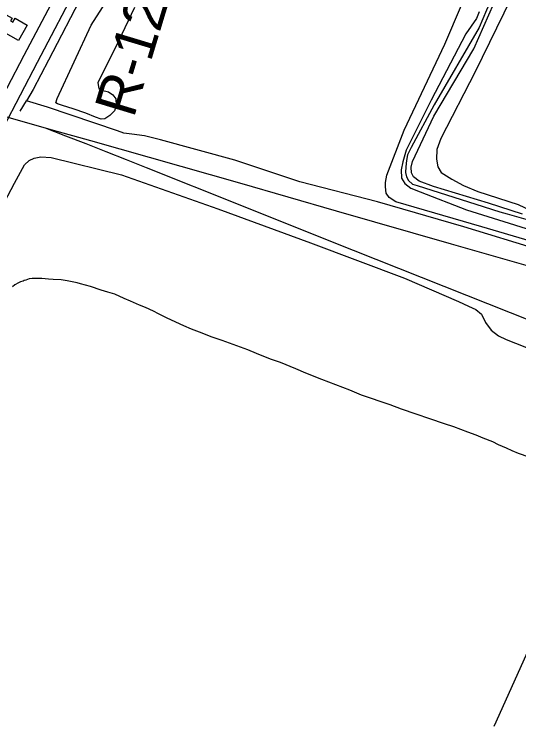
# Model space of a CAD drawing. Extents: x 3567028 to 3605064, y 510945 to 536587.
# Drawn here: x 3588639 to 3589650, y 520355 to 521776 of the extents above; entities that cross this region are included whole.
import ezdxf

# ---------------------------------------------------------------- set-up
doc = ezdxf.new("R2010")
doc.units = 0
for name, color, linetype in [('V-BLDG-OTLN', 7, 'Continuous'), ('V-RAIL-TRAK', 7, 'Continuous'), ('V-RIVR-RANG-IDEN', 7, 'Continuous'), ('V-ROAD-CNTR', 7, 'Continuous'), ('V-SITE-VEGE', 7, 'Continuous'), ('V-TOPO-SHOR', 7, 'Continuous')]:
    doc.layers.add(name, color=color, linetype=linetype)

msp = doc.modelspace()

# ---------------------------------------------------------------- linework, layer by layer
at = {"layer": 'V-BLDG-OTLN'}
msp.add_lwpolyline([(3588665.5, 521754.5), (3588648.2, 521723.7), (3588617.5, 521741), (3588614.2, 521735.2), (3588595.3, 521745.9), (3588600.1, 521754.3), (3588609.1, 521749.3), (3588623.6, 521775), (3588635.3, 521768.4), (3588632.2, 521763.1), (3588636.8, 521760.5), (3588641.2, 521768.2)], close=True, dxfattribs=at)
at = {"layer": 'V-RAIL-TRAK'}
for points in [[(3588149.4, 521708.3), (3588373.9, 521643.8), (3588624.2, 521571.2), (3588701.3, 521548.8), (3588712.7, 521545.5), (3588792.2, 521523.6), (3589090.5, 521438.9), (3589284.2, 521383.4), (3589514.3, 521317.3), (3589701.3, 521263.5)], [(3588701.3, 521548.8), (3588741.9, 521533.4), (3588782.5, 521517.8), (3588823, 521502), (3588863.3, 521486), (3588903.6, 521469.7), (3589091.4, 521395.1), (3589272.9, 521322.7), (3589499.9, 521232.4), (3589720.1, 521145.4)]]:
    msp.add_lwpolyline(points, dxfattribs=at)
at = {"layer": 'V-ROAD-CNTR'}
for points in [[(3588939.5, 522164.8), (3588685.5, 521679.8), (3588548.3, 521418.6), (3588324.5, 520986.4), (3588212.6, 520770.2), (3587956.4, 520279.2), (3587855.8, 520084.1), (3587648.7, 519691.3), (3587418.1, 519252.9), (3587233.2, 518901.5), (3587118.4, 518681.4), (3586962.3, 518388.3), (3586789.7, 518038.8)], [(3588736.5, 521841.8), (3588658.9, 521693.7), (3588521.7, 521432.4), (3588297.8, 521000.2), (3588244.5, 520897.2)]]:
    msp.add_lwpolyline(points, dxfattribs=at)
at = {"layer": 'V-SITE-VEGE'}
for p, q in [((3588660.2, 521474.9), (3588669.1, 521483.8)), ((3588669.1, 521483.8), (3588679.7, 521488.6)), ((3588679.7, 521488.6), (3588692.7, 521490.9)), ((3588692.7, 521490.9), (3588713.5, 521489.7)), ((3588713.5, 521489.7), (3588854.3, 521455.3)), ((3588640, 521438.3), (3588660.2, 521474.9)), ((3588854.3, 521455.3), (3589047.2, 521387.1)), ((3588584.9, 521335.3), (3588640, 521438.3)), ((3589047.2, 521387.1), (3589232.4, 521319)), ((3589232.4, 521319), (3589420.6, 521248.4)), ((3588648.1, 521239.4), (3588640.8, 521234.9)), ((3588651.7, 521241.2), (3588648.1, 521239.4)), ((3588654.4, 521241.6), (3588651.7, 521241.2)), ((3588657.1, 521242.5), (3588654.4, 521241.6)), ((3588659.4, 521243.8), (3588657.1, 521242.5)), ((3588662.6, 521244.2), (3588659.4, 521243.8)), ((3588669.4, 521246.9), (3588662.6, 521244.2)), ((3588675.7, 521247.8), (3588669.4, 521246.9)), ((3588694.7, 521247.6), (3588675.7, 521247.8)), ((3588708.2, 521246.6), (3588694.7, 521247.6)), ((3588717.7, 521245.7), (3588708.2, 521246.6)), ((3588733.6, 521245.1), (3588717.7, 521245.7)), ((3588745.3, 521243.2), (3588733.6, 521245.1)), ((3588765.2, 521239), (3588745.3, 521243.2)), ((3588771.9, 521237.2), (3588765.2, 521239)), ((3588792.2, 521232), (3588771.9, 521237.2)), ((3589420.6, 521248.4), (3589528.9, 521201.6)), ((3588640.8, 521234.9), (3588635.8, 521230.9)), ((3588813.4, 521224.7), (3588792.2, 521232)), ((3588827, 521220.5), (3588813.4, 521224.7)), ((3588841, 521216.3), (3588827, 521220.5)), ((3588859.9, 521207.6), (3588841, 521216.3)), ((3588872.1, 521202.6), (3588859.9, 521207.6)), ((3588890.1, 521194.7), (3588872.1, 521202.6)), ((3588902.3, 521189.7), (3588890.1, 521194.7)), ((3589528.9, 521201.6), (3589549, 521192.7)), ((3588918, 521182.3), (3588902.3, 521189.7)), ((3588928.4, 521177.3), (3588918, 521182.3)), ((3589549, 521192.7), (3589563.8, 521185.6)), ((3589563.8, 521185.6), (3589575, 521176.1)), ((3588946, 521168.1), (3588928.4, 521177.3)), ((3588979.3, 521153), (3588946, 521168.1)), ((3589575, 521176.1), (3589583.3, 521159.5)), ((3588994.6, 521146.5), (3588979.3, 521153)), ((3589583.3, 521159.5), (3589594.6, 521144.7)), ((3589010.4, 521140.1), (3588994.6, 521146.5)), ((3589036.1, 521130.4), (3589010.4, 521140.1)), ((3589594.6, 521144.7), (3589608.8, 521132.9)), ((3589056, 521124), (3589036.1, 521130.4)), ((3589106.9, 521105.1), (3589056, 521124)), ((3589608.8, 521132.9), (3589624.7, 521125.8)), ((3589624.7, 521125.8), (3589712.3, 521090.8)), ((3589124.5, 521097.7), (3589106.9, 521105.1)), ((3589152.5, 521086.7), (3589124.5, 521097.7)), ((3589172.3, 521079.8), (3589152.5, 521086.7)), ((3589203, 521067.3), (3589172.3, 521079.8)), ((3589223.2, 521058.6), (3589203, 521067.3)), ((3589255.3, 521045.7), (3589223.2, 521058.6)), ((3589311.6, 521024.1), (3589255.3, 521045.7)), ((3589335.1, 521014.4), (3589311.6, 521024.1)), ((3589391.9, 520995.1), (3589335.1, 521014.4)), ((3589414.9, 520986.3), (3589391.9, 520995.1)), ((3589501, 520957.2), (3589414.9, 520986.3)), ((3589519.5, 520950.8), (3589501, 520957.2)), ((3589547.9, 520940.6), (3589519.5, 520950.8)), ((3589564.2, 520934.2), (3589547.9, 520940.6)), ((3589578.6, 520928.7), (3589564.2, 520934.2)), ((3589598, 520920.8), (3589578.6, 520928.7)), ((3589609.2, 520915.3), (3589598, 520920.8)), ((3589625, 520908.4), (3589609.2, 520915.3)), ((3589636.7, 520902.9), (3589625, 520908.4)), ((3589649.4, 520897.9), (3589636.7, 520902.9)), ((3589670.6, 520890.5), (3589649.4, 520897.9)), ((3589604.1, 520361.1), (3589672.9, 520513.4)), ((3589600.4, 520352.1), (3589604.1, 520361.1))]:
    msp.add_line(p, q, dxfattribs=at)
for points in [[(3589657, 521376.1), (3589589.4, 521398.7), (3589479.2, 521432), (3589450.1, 521442.1), (3589438.9, 521451), (3589434.7, 521459.3), (3589434.1, 521470.6), (3589437.1, 521481.8), (3589479.3, 521572.5), (3589559.4, 521707.1), (3589599.8, 521797.8), (3589605.1, 521825.1), (3589602.2, 521840.5), (3589600.4, 521851.1), (3589600.4, 521865.4), (3589602.8, 521875.5), (3589612.9, 521889.1), (3589615, 521890.8), (3589628.7, 521902.7), (3589664.1, 521962.5)], [(3589770.8, 521293.9), (3589575.8, 521350.9), (3589403.8, 521401.4), (3589390.2, 521409.7), (3589384.3, 521418.6), (3589383.1, 521431.1), (3589383.1, 521440), (3589385.5, 521454.2), (3589419.9, 521544.3), (3589501.9, 521716.2), (3589570.7, 521878)], [(3588880.3, 521790.1), (3588847.9, 521722.5), (3588806.6, 521639.4), (3588809, 521628), (3588814.4, 521624.4), (3588828.1, 521620.8), (3588837.1, 521614.8), (3588843.1, 521607.1), (3588843.7, 521593.9), (3588840.1, 521583.1), (3588831.1, 521573.6), (3588820.9, 521567), (3588813.8, 521566.4), (3588802.4, 521570.6), (3588782.7, 521578.4), (3588757.5, 521586.8), (3588736, 521594), (3588725.8, 521597), (3588722.8, 521599.4), (3588725.2, 521607.7), (3588793.5, 521754.3), (3588861.8, 521861.3)], [(3589653.7, 521847.8), (3589633.6, 521807.8), (3589562.3, 521661.4), (3589493.5, 521528), (3589485.7, 521506.1), (3589485.1, 521486.5), (3589487.5, 521471.1), (3589494.6, 521459.9), (3589515.4, 521446.2), (3589539.1, 521433.7), (3589567.5, 521421.9), (3589648.7, 521395.7), (3589673.6, 521383.8)], [(3589570.7, 521781.4), (3589565.3, 521767.8), (3589544, 521736.9), (3589474.5, 521604.7), (3589424, 521504.6), (3589417.5, 521481.4), (3589414.5, 521465.4), (3589415.1, 521448.2), (3589421.6, 521437.6), (3589433.5, 521428.7), (3589452.5, 521420.9), (3589544.9, 521385.3), (3589739.4, 521324.7)]]:
    msp.add_lwpolyline(points, dxfattribs=at)
at = {"layer": 'V-TOPO-SHOR'}
msp.add_line((3588651.3, 521582.7), (3588663.9, 521602.8), dxfattribs=at)
for points in [[(3589341.4, 521997.5), (3589425, 521956.7), (3589560.1, 521893.2), (3589591.5, 521878.9), (3589595.7, 521871.8), (3589593.3, 521850.5), (3589595.1, 521816.1), (3589592.1, 521800.1), (3589585, 521784.6), (3589570.7, 521749.7), (3589480.5, 521595), (3589434.2, 521509.6), (3589427.1, 521495.4), (3589424.7, 521484.1), (3589423.5, 521471.1), (3589422.9, 521459.8), (3589424.7, 521450.9), (3589428.8, 521443.8), (3589437.1, 521436.7), (3589446, 521433.7), (3589564, 521396.3), (3589612, 521381.4)], [(3588837.9, 521941.9), (3588777.9, 521819.8), (3588708.4, 521684.6), (3588677.6, 521626), (3588663.9, 521602.8)], [(3591205.5, 520869.1), (3591079.3, 520900), (3590907.9, 520948.1), (3590756.1, 520994.4), (3590634, 521031.9), (3590469.8, 521081.2), (3590287.8, 521135.2), (3590133.1, 521181), (3589996.7, 521218.4), (3589853.8, 521260), (3589692.5, 521304.6), (3589539.6, 521350.9), (3589366.5, 521401.4), (3589211.1, 521441.2), (3589081.3, 521484.6), (3588932.5, 521525), (3588900.5, 521533.3), (3588875, 521536.3), (3588859, 521538.7), (3588846.5, 521543.4), (3588706, 521590.4), (3588663.9, 521602.8)], [(3589612, 521381.4), (3589626.2, 521377.2), (3589738.3, 521345.1), (3589867.5, 521309.5), (3590019.3, 521269), (3590179.4, 521219.7), (3590311, 521182.9), (3590489.4, 521127.6), (3590647.7, 521085.5), (3590798.9, 521043.9), (3590980.9, 520990.4), (3591141, 520945.2), (3591278.3, 520907)]]:
    msp.add_lwpolyline(points, dxfattribs=at)

# ---------------------------------------------------------------- texts
at = {"layer": 'V-RIVR-RANG-IDEN'}
msp.add_text('R-120.6', height=83, rotation=73.2241, dxfattribs=at).set_placement((3588878.7, 521566.9))

doc.saveas('drawing.dxf')
